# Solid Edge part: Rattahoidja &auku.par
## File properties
Author: Türk
Template: fop_flange.par
Last saved by: rkriggs
Revision: 8
Application: Solid Edge
Face Style: Model Default
Coef. of Thermal Exp: 0.0
Thermal Conductivity: 0.0
Specific Heat: 0.0
Modulus of Elasticity: 0.0
Poisson's Ratio: 0.0
Yield Stress: 0.0
Ultimate Stress: 0.0
Elongation: 0.0
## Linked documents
fop_flange.par
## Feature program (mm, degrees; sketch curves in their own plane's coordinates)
part copy "CopiedPart_1"
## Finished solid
Body 1: solid body, 25 faces, 54 edges, 24 vertices.
  Faces by surface: cylinder 20, plane 3, cone 1, torus 1
  Edges by curve: circle 42, line 12
Bounding box of the edges (mm; curved faces can reach further): 180.000 x 161.780 x 75.000, from (-90, -80.8897, -25) to (90, 80.8897, 50).
Cylindrical faces by radius (mm): R11 x6, R22 x6, R27.5 x1, R42.5 x1, R80 x6
Conical faces (half-angle, radius in mm at the cone's reference point): 45 deg R30.5 x1
Toroidal faces (ring radius, tube radius in mm): R47.5 r5 x1
Planar faces by outward normal: +z 2, -z 1
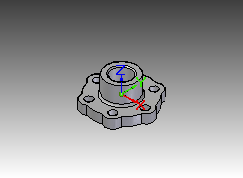
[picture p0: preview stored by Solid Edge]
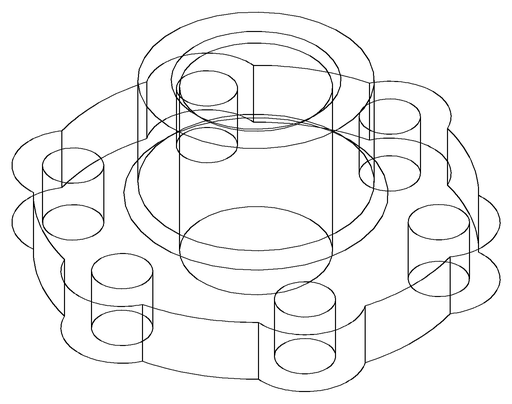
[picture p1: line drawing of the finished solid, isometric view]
